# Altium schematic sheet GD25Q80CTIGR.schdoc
size 127 x 101 mm
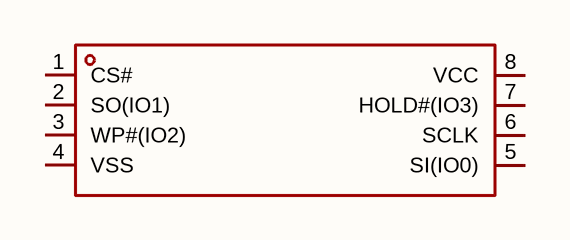
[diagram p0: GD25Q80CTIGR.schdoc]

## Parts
U?  gd25q80ctigr  [SOP-8_L5.0-W4.0-P1.27-LS6.0-BL]  (value not drawn)

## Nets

Not connected (* = marked no-connect by the designer): U? 1(CS#) 2(SO(IO1)) 3(WP#(IO2)) 4(VSS) 5(SI(IO0)) 6(SCLK) 7(HOLD#(IO3)) 8(VCC)

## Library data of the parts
U? = gd25q80ctigr: 接口类型:SPI;存储容量:8Mbit;时钟频率(fc):120MHz;; Manufacturer: GigaDevice(兆易创新); AddInBom: yes; ModelId: a3315c1c78f949e6bb82c6eaca1c53c7; ModelName: SOP-8_L5.0-W4.0-H1.8-LS6.2-P1.27; ModelTransform: 244.094,196.85,0,90,0,0,0,0,0; Interface: SPI; Memory Size: 8Mbit; Clock Frequency: 120MHz; Voltage - Supply: 2.7V~3.6V; Standby Supply Current: 1uA; Program / Erase Cycles: 100000次; Page Programming Time (Tpp): 600us; Data Retention - TDR (Year): 20年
